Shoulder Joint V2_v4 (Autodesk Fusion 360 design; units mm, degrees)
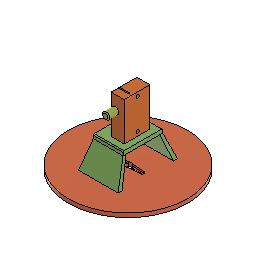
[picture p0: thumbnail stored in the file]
component_insert "Component Insert1"
component_insert "Component Insert2"
joint "Assemble" alignAngle 180 alignOffsetX 0 alignOffsetY -22.55 (= "-24.59 mm + 2.04 mm") alignOffsetZ 0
